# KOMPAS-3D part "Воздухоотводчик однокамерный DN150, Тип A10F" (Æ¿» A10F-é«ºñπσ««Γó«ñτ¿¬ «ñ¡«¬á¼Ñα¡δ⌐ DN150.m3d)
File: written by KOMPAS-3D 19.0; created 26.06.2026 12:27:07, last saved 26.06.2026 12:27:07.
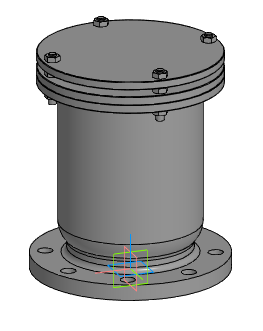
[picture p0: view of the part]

Document properties: Автор: Энергия; Полное имя файла: Z:\3.Личные\kachalov\001_3d для проектировщиков\х.х Тип A10F Воздухоотводчик однокамерный фланцевый\_step\Тип A10F-Воздухоотводчик однокамерный DN150.m3d

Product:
- Part/product: Воздухоотводчик однокамерный DN150  | designation Тип A10F

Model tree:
1. Операция без истории:1  (labels: Тип A10F; Воздухоотводчик однокамерный DN150)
